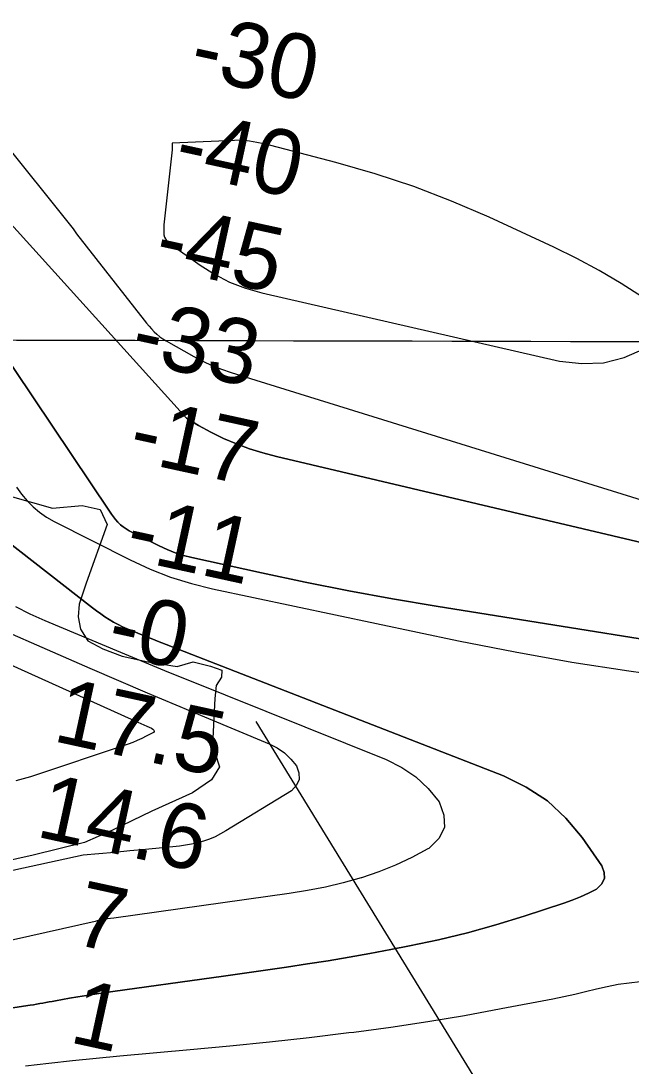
# Model space of a CAD drawing. Extents: x 3161615 to 3199515, y 867541 to 892976.
# Drawn here: x 3188262 to 3188892, y 878257 to 879335 of the extents above; entities that cross this region are included whole.
import ezdxf

# ---------------------------------------------------------------- set-up
doc = ezdxf.new("R2010")
doc.units = 0
for name, color, linetype in [('V-GRID-MAJR', 7, 'Continuous'), ('V-RIVR-EDGE', 7, 'Continuous'), ('V-RIVR-RANG', 7, 'Continuous'), ('V-TOPO-DPTH', 7, 'Continuous'), ('V-TOPO-MAJR', 7, 'Continuous'), ('V-TOPO-MINR', 7, 'Continuous'), ('V-TOPO-WATR', 7, 'Continuous')]:
    doc.layers.add(name, color=color, linetype=linetype)

msp = doc.modelspace()

# ---------------------------------------------------------------- linework, layer by layer
at = {"layer": 'V-GRID-MAJR'}
msp.add_spline([(3165838.644, 879070.158), (3171065.6580000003, 879053.813), (3176292.6750000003, 879038.2270000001), (3181519.694, 879023.402), (3186746.716, 879009.337), (3191973.739, 878996.033), (3197200.764, 878983.488), (3197200.765, 878983.488)], degree=3, dxfattribs=at)
at = {"layer": 'V-RIVR-EDGE'}
msp.add_lwpolyline([(3188253.595001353, 878843.9909423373), (3188295.054610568, 878832.4434141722), (3188325.5815268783, 878835.2291824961), (3188344.168942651, 878830.8913422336), (3188351.2842970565, 878815.6137340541), (3188329.6752792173, 878755.1039865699), (3188322.467949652, 878733.1855381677), (3188321.4823670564, 878720.3123384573), (3188323.8348921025, 878707.4308845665), (3188331.435373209, 878695.4902048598), (3188346.67524799, 878687.3456386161), (3188366.6850271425, 878679.6661532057), (3188393.375738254, 878673.8776495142), (3188423.4069153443, 878669.0346366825), (3188440.109245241, 878673.7620909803), (3188457.742915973, 878669.426609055), (3188469.654116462, 878665.105277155), (3188469.1595564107, 878657.9533685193), (3188463.8927336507, 878649.3826340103), (3188462.4290993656, 878636.0337409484), (3188460.4202007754, 878595.0274208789), (3188462.291136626, 878580.2396560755), (3188467.023307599, 878565.4448162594), (3188458.88345803, 878552.1124315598), (3188439.298667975, 878538.8083469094), (3188397.286719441, 878519.837212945), (3188356.226157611, 878499.9099756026), (3188328.060020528, 878487.5808610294), (3188275.094154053, 878474.359318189), (3188241.2173384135, 878466.8130788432)], dxfattribs=at)
at = {"layer": 'V-RIVR-RANG'}
msp.add_line((3189132.631400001, 877589.6579999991), (3188504.9442000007, 878612.4036999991), dxfattribs=at)
at = {"layer": 'V-TOPO-DPTH'}
for points in [[(3188238.429682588, 879217.0326546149), (3188316.2582709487, 879120.4139114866), (3188319.635606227, 879115.3042481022), (3188389.4831320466, 879026.146056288), (3188391.9484583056, 879023.0972848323), (3188394.4746137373, 879020.1014330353), (3188397.092012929, 879017.1849607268), (3188399.770241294, 879014.3214080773), (3188402.600257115, 879011.6350932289), (3188405.569195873, 879009.12882298), (3188408.746519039, 879006.8926196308), (3188412.0627651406, 879004.8364608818), (3188440.568142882, 878988.8550906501), (3188449.889710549, 878984.008384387), (3188459.384973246, 878979.5655225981), (3188469.1407784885, 878975.7284275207), (3188479.070278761, 878972.2951769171), (3188962.946035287, 878821.8761231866)], [(3188238.429682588, 879217.0326546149), (3188316.2582709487, 879120.4139114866), (3188319.635606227, 879115.3042481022), (3188389.4831320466, 879026.146056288), (3188391.9484583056, 879023.0972848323), (3188394.4746137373, 879020.1014330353), (3188397.092012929, 879017.1849607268), (3188399.770241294, 879014.3214080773), (3188402.600257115, 879011.6350932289), (3188405.569195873, 879009.12882298), (3188408.746519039, 879006.8926196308), (3188412.0627651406, 879004.8364608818), (3188440.568142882, 878988.8550906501), (3188449.889710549, 878984.008384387), (3188459.384973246, 878979.5655225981), (3188469.1407784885, 878975.7284275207), (3188479.070278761, 878972.2951769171), (3188962.946035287, 878821.8761231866)], [(3189047.403530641, 878674.225311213), (3188690.8657579, 878731.3461501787), (3188645.6347427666, 878738.9944267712), (3188600.5024084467, 878747.1622901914), (3188555.518095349, 878756.1095338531), (3188510.6324630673, 878765.5763643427), (3188438.6060418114, 878781.4193562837), (3188429.922612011, 878783.6771339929), (3188421.3904130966, 878786.3592519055), (3188413.085060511, 878789.6778801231), (3188404.9309388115, 878793.4208485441), (3188373.930528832, 878809.0978803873), (3188370.7828190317, 878810.905143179), (3188367.7874312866, 878812.9153551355), (3188365.0205266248, 878815.2299908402), (3188362.405944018, 878817.7475757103), (3188360.0018664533, 878820.4915803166), (3188357.721016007, 878823.3283717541), (3188355.6250062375, 878826.3043434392), (3188353.6522235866, 878829.3731019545), (3188097.792003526, 879209.9937966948)], [(3189047.403530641, 878674.225311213), (3188690.8657579, 878731.3461501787), (3188645.6347427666, 878738.9944267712), (3188600.5024084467, 878747.1622901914), (3188555.518095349, 878756.1095338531), (3188510.6324630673, 878765.5763643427), (3188438.6060418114, 878781.4193562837), (3188429.922612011, 878783.6771339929), (3188421.3904130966, 878786.3592519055), (3188413.085060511, 878789.6778801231), (3188404.9309388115, 878793.4208485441), (3188373.930528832, 878809.0978803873), (3188370.7828190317, 878810.905143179), (3188367.7874312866, 878812.9153551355), (3188365.0205266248, 878815.2299908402), (3188362.405944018, 878817.7475757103), (3188360.0018664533, 878820.4915803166), (3188357.721016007, 878823.3283717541), (3188355.6250062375, 878826.3043434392), (3188353.6522235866, 878829.3731019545), (3188097.792003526, 879209.9937966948)], [(3188203.1891735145, 879179.2378905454), (3188433.301359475, 878925.2373128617), (3188445.571534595, 878917.5798306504), (3188458.2858328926, 878910.6848433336), (3188471.2962133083, 878904.2981859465), (3188484.667643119, 878898.6978247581), (3188498.2204028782, 878893.6289504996), (3188512.0451575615, 878889.3573066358), (3188526.051242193, 878885.6171497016), (3189049.484469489, 878762.0639388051), (3189069.719366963, 878757.8251826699), (3189090.0565771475, 878754.2748056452), (3189110.5472563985, 878751.7569972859), (3189131.140248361, 878749.9275680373), (3189255.383497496, 878742.0529966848), (3189338.179173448, 878738.3195993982), (3189420.9799930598, 878736.5986324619), (3189503.788528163, 878737.8963110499), (3189586.602206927, 878741.2064199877)], [(3189586.602206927, 878741.2064199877), (3189503.788528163, 878737.8963110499), (3189420.9799930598, 878736.5986324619), (3189338.179173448, 878738.3195993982), (3189255.383497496, 878742.0529966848), (3189131.140248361, 878749.9275680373), (3189110.5472563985, 878751.7569972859), (3189090.0565771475, 878754.2748056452), (3189069.719366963, 878757.8251826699), (3189049.484469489, 878762.0639388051), (3188526.051242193, 878885.6171497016), (3188512.0451575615, 878889.3573066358), (3188498.2204028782, 878893.6289504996), (3188484.667643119, 878898.6978247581), (3188471.2962133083, 878904.2981859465), (3188458.2858328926, 878910.6848433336), (3188445.571534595, 878917.5798306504), (3188433.301359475, 878925.2373128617), (3188203.1891735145, 879179.2378905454)], [(3188213.793076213, 878824.6183972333), (3188336.15234488, 878729.4626898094), (3188340.34274863, 878726.3103720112), (3188344.5970564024, 878723.2499584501), (3188348.947220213, 878720.3274012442), (3188353.3612880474, 878717.4967482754), (3188357.88273423, 878714.8515834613), (3188362.4828453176, 878712.3607302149), (3188367.2009537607, 878710.1013443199), (3188371.997727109, 878707.9962699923), (3188393.9954657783, 878698.9877367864), (3188398.5388031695, 878697.1410916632), (3188403.0885218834, 878695.3104272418), (3188407.647812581, 878693.5037338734), (3188412.2134846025, 878691.7130212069), (3188760.013834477, 878556.3564308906), (3188783.6453897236, 878544.6293028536), (3188805.39121786, 878530.4964830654), (3188824.3084553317, 878512.7551256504), (3188841.339965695, 878492.6080764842), (3188861.715605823, 878463.597039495), (3188864.0809646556, 878456.7055363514), (3188864.294501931, 878450.3150072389), (3188861.280306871, 878444.6759391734), (3188856.114290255, 878439.537845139), (3188847.887690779, 878435.3237812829), (3188839.526070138, 878431.4211515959), (3188830.961917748, 878427.985673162), (3188822.2627441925, 878424.8616288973), (3188781.623274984, 878411.5224690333), (3188752.3559586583, 878402.528464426), (3188722.894057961, 878394.2844746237), (3188693.1402807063, 878387.165507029), (3188663.1919190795, 878380.7965542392), (3188643.880226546, 878377.0717938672), (3188622.4203582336, 878373.0646602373), (3188600.9311375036, 878369.2277520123), (3188579.397888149, 878365.6461818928), (3188557.835286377, 878362.2348371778), (3188536.2446509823, 878358.9924903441), (3188514.645999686, 878355.8051912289), (3188493.0353245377, 878352.7004636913), (3188471.416633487, 878349.6507838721), (3188347.239896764, 878332.3755233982), (3188338.5293668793, 878331.1138649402), (3188329.8291277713, 878329.78717207), (3188321.1443248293, 878328.3629275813), (3188312.4698126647, 878326.8736486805), (3188297.830776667, 878324.275703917), (3188294.6078618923, 878323.699368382), (3188291.3859754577, 878323.1173824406), (3188288.165631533, 878322.5269208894), (3188284.9463159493, 878321.9308089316), (3188281.7250189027, 878321.3467282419), (3188278.5000524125, 878320.78433464), (3188275.2695817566, 878320.2544716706), (3188272.035441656, 878319.7462957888), (3188104.1751442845, 878294.2367667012)], [(3188104.1751442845, 878294.2367667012), (3188272.035441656, 878319.7462957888), (3188275.2695817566, 878320.2544716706), (3188278.5000524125, 878320.78433464), (3188281.7250189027, 878321.3467282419), (3188284.9463159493, 878321.9308089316), (3188288.165631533, 878322.5269208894), (3188291.3859754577, 878323.1173824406), (3188294.6078618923, 878323.699368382), (3188297.830776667, 878324.275703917), (3188312.4698126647, 878326.8736486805), (3188321.1443248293, 878328.3629275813), (3188329.8291277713, 878329.78717207), (3188338.5293668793, 878331.1138649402), (3188347.239896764, 878332.3755233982), (3188471.416633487, 878349.6507838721), (3188493.0353245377, 878352.7004636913), (3188514.645999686, 878355.8051912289), (3188536.2446509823, 878358.9924903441), (3188557.835286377, 878362.2348371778), (3188579.397888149, 878365.6461818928), (3188600.9311375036, 878369.2277520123), (3188622.4203582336, 878373.0646602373), (3188643.880226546, 878377.0717938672), (3188663.1919190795, 878380.7965542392), (3188693.1402807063, 878387.165507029), (3188722.894057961, 878394.2844746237), (3188752.3559586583, 878402.528464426), (3188781.623274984, 878411.5224690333), (3188822.2627441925, 878424.8616288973), (3188830.961917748, 878427.985673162), (3188839.526070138, 878431.4211515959), (3188847.887690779, 878435.3237812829), (3188856.114290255, 878439.537845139), (3188861.280306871, 878444.6759391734), (3188864.294501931, 878450.3150072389), (3188864.0809646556, 878456.7055363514), (3188861.715605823, 878463.597039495), (3188841.339965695, 878492.6080764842), (3188824.3084553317, 878512.7551256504), (3188805.39121786, 878530.4964830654), (3188783.6453897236, 878544.6293028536), (3188760.013834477, 878556.3564308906), (3188412.2134846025, 878691.7130212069), (3188407.647812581, 878693.5037338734), (3188403.0885218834, 878695.3104272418), (3188398.5388031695, 878697.1410916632), (3188393.9954657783, 878698.9877367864), (3188371.997727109, 878707.9962699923), (3188367.2009537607, 878710.1013443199), (3188362.4828453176, 878712.3607302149), (3188357.88273423, 878714.8515834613), (3188353.3612880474, 878717.4967482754), (3188348.947220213, 878720.3274012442), (3188344.5970564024, 878723.2499584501), (3188340.34274863, 878726.3103720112), (3188336.15234488, 878729.4626898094), (3188213.793076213, 878824.6183972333)], [(3188197.850024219, 878726.3525696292), (3188333.4469428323, 878667.450468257), (3188362.9617268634, 878654.7068121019), (3188392.5135382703, 878642.0501400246), (3188422.120890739, 878629.5239440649), (3188451.7652705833, 878617.084732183), (3188518.3397858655, 878589.3216254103), (3188526.5707417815, 878585.019024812), (3188534.146412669, 878579.9051786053), (3188540.7391560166, 878573.574463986), (3188546.6766143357, 878566.4325037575), (3188549.187340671, 878559.2474368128), (3188549.4997048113, 878552.522921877), (3188546.5145256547, 878546.4892349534), (3188541.330984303, 878540.9161000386), (3188473.8108124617, 878499.4464019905), (3188468.2635784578, 878496.3174136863), (3188462.586156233, 878493.4744712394), (3188456.713451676, 878491.0605975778), (3188450.710558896, 878488.9327697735), (3188444.5692658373, 878487.2166569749), (3188438.3757606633, 878485.7575017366), (3188432.103937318, 878484.6837828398), (3188425.779901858, 878483.867021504), (3188390.8426794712, 878480.450281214), (3188374.8051240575, 878478.9003380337), (3188358.7652753, 878477.3748031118), (3188342.7219865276, 878475.8858805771), (3188326.676404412, 878474.4213663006), (3187958.566920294, 878394.2581927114)], [(3188197.850024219, 878726.3525696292), (3188333.4469428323, 878667.450468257), (3188362.9617268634, 878654.7068121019), (3188392.5135382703, 878642.0501400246), (3188422.120890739, 878629.5239440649), (3188451.7652705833, 878617.084732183), (3188518.3397858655, 878589.3216254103), (3188526.5707417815, 878585.019024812), (3188534.146412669, 878579.9051786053), (3188540.7391560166, 878573.574463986), (3188546.6766143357, 878566.4325037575), (3188549.187340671, 878559.2474368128), (3188549.4997048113, 878552.522921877), (3188546.5145256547, 878546.4892349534), (3188541.330984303, 878540.9161000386), (3188473.8108124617, 878499.4464019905), (3188468.2635784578, 878496.3174136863), (3188462.586156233, 878493.4744712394), (3188456.713451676, 878491.0605975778), (3188450.710558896, 878488.9327697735), (3188444.5692658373, 878487.2166569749), (3188438.3757606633, 878485.7575017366), (3188432.103937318, 878484.6837828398), (3188425.779901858, 878483.867021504), (3188390.8426794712, 878480.450281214), (3188374.8051240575, 878478.9003380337), (3188358.7652753, 878477.3748031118), (3188342.7219865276, 878475.8858805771), (3188326.676404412, 878474.4213663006), (3187958.566920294, 878394.2581927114)]]:
    msp.add_lwpolyline(points, dxfattribs=at)
at = {"layer": 'V-TOPO-MAJR'}
for points in [[(3188903.617624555, 879049.974967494), (3188881.4618727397, 879064.1399470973), (3188858.894736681, 879077.5746827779), (3188835.710524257, 879089.9140525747), (3188812.1149275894, 879101.5231784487), (3188745.277375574, 879132.4414470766), (3188706.6544131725, 879149.0562235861), (3188667.5229102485, 879164.2484544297), (3188627.6285965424, 879177.3068667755), (3188587.225742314, 879188.9427334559), (3188520.2771216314, 879206.2790594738), (3188512.9379110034, 879208.0351470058), (3188505.56323795, 879209.6084955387), (3188498.13537126, 879210.9077355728), (3188490.6720421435, 879212.0242366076), (3188418.2238840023, 879208.7551103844), (3188418.4058306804, 879205.3356947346), (3188418.27335034, 879201.8775347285), (3188409.885248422, 879124.6702718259), (3188409.6904047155, 879122.0621361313), (3188409.612401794, 879119.4544318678), (3188409.70966005, 879116.8473747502), (3188409.9237590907, 879114.2407490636), (3188410.5305450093, 879111.8142221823), (3188412.970610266, 879107.6861346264), (3188414.8038896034, 879105.9845739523), (3188447.2113568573, 879082.9112384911), (3188462.1412388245, 879073.5659721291), (3188477.63528028, 879065.4772819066), (3188493.975560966, 879059.2734558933), (3188510.8800011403, 879054.3262060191), (3188818.0265733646, 878983.9411365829), (3188840.849808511, 878981.3996587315), (3188863.184807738, 878982.1643171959)], [(3188863.184807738, 878982.1643171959), (3188884.787453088, 878987.8881801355), (3188905.901862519, 878996.9181793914)]]:
    msp.add_lwpolyline(points, dxfattribs=at)
at = {"layer": 'V-TOPO-MINR'}
for points in [[(3188238.429682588, 879217.0326546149), (3188316.2582709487, 879120.4139114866), (3188319.635606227, 879115.3042481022), (3188389.4831320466, 879026.146056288), (3188391.9484583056, 879023.0972848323), (3188394.4746137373, 879020.1014330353), (3188397.092012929, 879017.1849607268), (3188399.770241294, 879014.3214080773), (3188402.600257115, 879011.6350932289), (3188405.569195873, 879009.12882298), (3188408.746519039, 879006.8926196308), (3188412.0627651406, 879004.8364608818), (3188440.568142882, 878988.8550906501), (3188449.889710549, 878984.008384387), (3188459.384973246, 878979.5655225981), (3188469.1407784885, 878975.7284275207), (3188479.070278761, 878972.2951769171), (3188962.946035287, 878821.8761231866)], [(3188097.792003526, 879209.9937966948), (3188353.6522235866, 878829.3731019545), (3188355.6250062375, 878826.3043434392), (3188357.721016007, 878823.3283717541), (3188360.0018664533, 878820.4915803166), (3188362.405944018, 878817.7475757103), (3188365.0205266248, 878815.2299908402), (3188367.7874312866, 878812.9153551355), (3188370.7828190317, 878810.905143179), (3188373.930528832, 878809.0978803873), (3188404.9309388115, 878793.4208485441), (3188413.085060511, 878789.6778801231), (3188421.3904130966, 878786.3592519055), (3188429.922612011, 878783.6771339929), (3188438.6060418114, 878781.4193562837), (3188510.6324630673, 878765.5763643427), (3188555.518095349, 878756.1095338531), (3188600.5024084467, 878747.1622901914), (3188645.6347427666, 878738.9944267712), (3188690.8657579, 878731.3461501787), (3189047.403530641, 878674.225311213)], [(3189586.602206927, 878741.2064199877), (3189503.788528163, 878737.8963110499), (3189420.9799930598, 878736.5986324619), (3189338.179173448, 878738.3195993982), (3189255.383497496, 878742.0529966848), (3189131.140248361, 878749.9275680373), (3189110.5472563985, 878751.7569972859), (3189090.0565771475, 878754.2748056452), (3189069.719366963, 878757.8251826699), (3189049.484469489, 878762.0639388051), (3188526.051242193, 878885.6171497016), (3188512.0451575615, 878889.3573066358), (3188498.2204028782, 878893.6289504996), (3188484.667643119, 878898.6978247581), (3188471.2962133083, 878904.2981859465), (3188458.2858328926, 878910.6848433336), (3188445.571534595, 878917.5798306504), (3188433.301359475, 878925.2373128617), (3188203.1891735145, 879179.2378905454)], [(3188257.6065705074, 878853.973754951), (3188262.926705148, 878846.8734534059), (3188268.6224744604, 878840.0325941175), (3188274.909283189, 878833.7882680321), (3188281.591874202, 878828.0613418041), (3188288.868138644, 878823.1105153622), (3188296.54018537, 878818.677088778), (3188375.1484831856, 878778.9251161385), (3188395.7001554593, 878769.5250964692), (3188416.641248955, 878761.2334087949), (3188438.166474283, 878754.604219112), (3188460.0811208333, 878749.0833614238), (3188713.8012522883, 878695.6481670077), (3188772.187840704, 878684.1055600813), (3188830.7371468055, 878673.5325986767), (3188889.5305294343, 878664.4141055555), (3188948.4866297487, 878656.265257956)], [(3188213.793076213, 878824.6183972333), (3188336.15234488, 878729.4626898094), (3188340.34274863, 878726.3103720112), (3188344.5970564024, 878723.2499584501), (3188348.947220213, 878720.3274012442), (3188353.3612880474, 878717.4967482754), (3188357.88273423, 878714.8515834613), (3188362.4828453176, 878712.3607302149), (3188367.2009537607, 878710.1013443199), (3188371.997727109, 878707.9962699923), (3188393.9954657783, 878698.9877367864), (3188398.5388031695, 878697.1410916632), (3188403.0885218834, 878695.3104272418), (3188407.647812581, 878693.5037338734), (3188412.2134846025, 878691.7130212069), (3188760.013834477, 878556.3564308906), (3188783.6453897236, 878544.6293028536), (3188805.39121786, 878530.4964830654), (3188824.3084553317, 878512.7551256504), (3188841.339965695, 878492.6080764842), (3188861.715605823, 878463.597039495), (3188864.0809646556, 878456.7055363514), (3188864.294501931, 878450.3150072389), (3188861.280306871, 878444.6759391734), (3188856.114290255, 878439.537845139), (3188847.887690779, 878435.3237812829), (3188839.526070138, 878431.4211515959), (3188830.961917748, 878427.985673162), (3188822.2627441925, 878424.8616288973), (3188781.623274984, 878411.5224690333), (3188752.3559586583, 878402.528464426), (3188722.894057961, 878394.2844746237), (3188693.1402807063, 878387.165507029), (3188663.1919190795, 878380.7965542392), (3188643.880226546, 878377.0717938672), (3188622.4203582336, 878373.0646602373), (3188600.9311375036, 878369.2277520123), (3188579.397888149, 878365.6461818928), (3188557.835286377, 878362.2348371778), (3188536.2446509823, 878358.9924903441), (3188514.645999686, 878355.8051912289), (3188493.0353245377, 878352.7004636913), (3188471.416633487, 878349.6507838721), (3188347.239896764, 878332.3755233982), (3188338.5293668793, 878331.1138649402), (3188329.8291277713, 878329.78717207), (3188321.1443248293, 878328.3629275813), (3188312.4698126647, 878326.8736486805), (3188297.830776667, 878324.275703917), (3188294.6078618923, 878323.699368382), (3188291.3859754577, 878323.1173824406), (3188288.165631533, 878322.5269208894), (3188284.9463159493, 878321.9308089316), (3188281.7250189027, 878321.3467282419), (3188278.5000524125, 878320.78433464), (3188275.2695817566, 878320.2544716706), (3188272.035441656, 878319.7462957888), (3188104.1751442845, 878294.2367667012)], [(3188105.525455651, 878736.8553920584), (3188379.8711821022, 878612.9163891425), (3188382.986525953, 878611.5161431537), (3188386.105395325, 878610.1238352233), (3188389.2295529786, 878608.7434343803), (3188392.357236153, 878607.3709715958), (3188397.09816109, 878605.3013744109), (3188398.4709601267, 878604.4594452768), (3188399.5611048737, 878603.2741156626), (3188399.782440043, 878602.0847084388), (3188399.042431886, 878601.1275946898), (3188391.5263113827, 878597.1035209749), (3188386.986010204, 878594.8191514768), (3188382.377718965, 878592.6925172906), (3188377.667442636, 878590.8024860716), (3188372.8891762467, 878589.0701901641), (3188272.0669233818, 878555.3911182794), (3188257.1995282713, 878550.9866385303)], [(3188256.763186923, 878730.9373961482), (3188271.6630740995, 878723.5213713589), (3188286.8474391, 878716.6398293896), (3188365.1025785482, 878683.7206045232), (3188381.5733616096, 878676.8392049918), (3188398.0662428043, 878670.011556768), (3188414.592271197, 878663.264535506), (3188431.1403977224, 878656.5712655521), (3188639.2875352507, 878572.9722087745), (3188655.16567803, 878564.9040685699), (3188669.7773247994, 878555.2422577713), (3188682.489227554, 878543.1899410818), (3188693.9346342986, 878529.5439537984), (3188698.668391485, 878515.8757956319), (3188699.175918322, 878503.1427344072), (3188693.344099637, 878491.8123185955), (3188683.286050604, 878481.4169997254), (3188682.269614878, 878480.8274618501), (3188665.746158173, 878472.0078000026), (3188648.874460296, 878463.9932364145), (3188631.480400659, 878457.1863202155), (3188613.7380998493, 878451.1845022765), (3188613.2610220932, 878451.0416683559), (3188594.9231736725, 878446.0044258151), (3188576.462167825, 878441.5313951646), (3188557.816425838, 878437.9046823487), (3188539.0475264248, 878434.8421814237), (3188358.028438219, 878409.5315534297), (3188354.818653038, 878409.0976711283), (3188351.611120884, 878408.6530044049), (3188347.3345894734, 878407.8734830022), (3188343.070607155, 878407.0258653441), (3188340.9445352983, 878406.5735308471), (3188338.821423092, 878406.1069335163), (3188183.883699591, 878371.2389128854)], [(3189029.367276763, 878321.8959144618), (3189026.111714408, 878326.1008482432), (3189015.1149761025, 878336.4976248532), (3189002.94974057, 878344.2642874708), (3188989.0317591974, 878348.0857790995), (3188973.945280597, 878349.2771567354), (3188901.200284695, 878343.7522648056), (3188889.7734579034, 878342.5754192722), (3188878.4139631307, 878340.9944255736), (3188867.155466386, 878338.8072096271), (3188855.964301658, 878336.2158455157), (3188844.799642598, 878333.4269142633), (3188833.6025711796, 878330.781280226)], [(3188833.6025711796, 878330.781280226), (3188822.3568812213, 878328.3505920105), (3188811.0787789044, 878326.0632010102), (3188757.9301009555, 878315.8127602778), (3188719.9924687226, 878308.8924751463), (3188681.973764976, 878302.4847223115), (3188643.833453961, 878296.8457679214), (3188605.612071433, 878291.7193458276), (3188600.519749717, 878291.0886080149), (3188559.6691467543, 878286.2396610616), (3188518.7889528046, 878281.6680903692), (3188477.8643723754, 878277.5125840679), (3188436.910200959, 878273.6344540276), (3188364.2021802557, 878267.1223611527), (3188339.8707821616, 878264.8233679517), (3188315.5561442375, 878262.3662419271), (3188291.2666465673, 878259.671916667), (3188266.9939090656, 878256.8194585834)]]:
    msp.add_lwpolyline(points, dxfattribs=at)
at = {"layer": 'V-TOPO-WATR'}
msp.add_lwpolyline([(3188197.850024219, 878726.3525696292), (3188333.4469428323, 878667.450468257), (3188362.9617268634, 878654.7068121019), (3188392.5135382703, 878642.0501400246), (3188422.120890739, 878629.5239440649), (3188451.7652705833, 878617.084732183), (3188518.3397858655, 878589.3216254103), (3188526.5707417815, 878585.019024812), (3188534.146412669, 878579.9051786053), (3188540.7391560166, 878573.574463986), (3188546.6766143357, 878566.4325037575), (3188549.187340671, 878559.2474368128), (3188549.4997048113, 878552.522921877), (3188546.5145256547, 878546.4892349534), (3188541.330984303, 878540.9161000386), (3188473.8108124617, 878499.4464019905), (3188468.2635784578, 878496.3174136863), (3188462.586156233, 878493.4744712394), (3188456.713451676, 878491.0605975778), (3188450.710558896, 878488.9327697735), (3188444.5692658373, 878487.2166569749), (3188438.3757606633, 878485.7575017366), (3188432.103937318, 878484.6837828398), (3188425.779901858, 878483.867021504), (3188390.8426794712, 878480.450281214), (3188374.8051240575, 878478.9003380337), (3188358.7652753, 878477.3748031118), (3188342.7219865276, 878475.8858805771), (3188326.676404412, 878474.4213663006), (3187958.566920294, 878394.2581927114)], dxfattribs=at)

# ---------------------------------------------------------------- texts
at = {"layer": 'V-RIVR-RANG'}
for s, p in [('-30', (3188434.181542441, 879278.1931695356)), ('-40', (3188418.248030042, 879179.3360411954)), ('-45', (3188397.932782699, 879081.4322829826)), ('-33', (3188373.2368004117, 878984.481894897)), ('-17', (3188371.221740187, 878882.5964143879)), ('-11', (3188367.9179343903, 878780.9913368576)), ('-0', (3188348.8914326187, 878682.8071756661)), ('17.5', (3188294.037803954, 878592.4182172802)), ('14.6', (3188276.557796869, 878493.897572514)), ('7', (3188314.2371002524, 878383.3756802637)), ('1', (3188310.9332944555, 878281.7706027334))]:
    msp.add_text(s, height=67, rotation=347.7249999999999, dxfattribs=at).set_placement(p)

doc.saveas('drawing.dxf')
